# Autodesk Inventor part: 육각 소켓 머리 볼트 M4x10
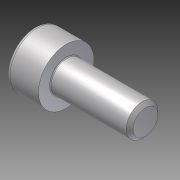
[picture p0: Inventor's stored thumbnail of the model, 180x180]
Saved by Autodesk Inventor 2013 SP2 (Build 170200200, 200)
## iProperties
Created: 2025-04
Part Number: 육각 소켓 머리 볼트 M4x10
Material: Generic
Document SubType Name: Modeling
Designer: 601
Density: 1 g/cm^3
Author: 601
변환 표준: STEP AP214IS
전처리기: Build: 200, Release: 2013 SP2 Update 6 - Date: Thu 07/17/2014
전송 단위: 밀리미터
불확실성: 0.01
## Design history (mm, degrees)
node "육각 소켓 머리 볼트 M4x101"
body "Solid1"
node "기준1"
